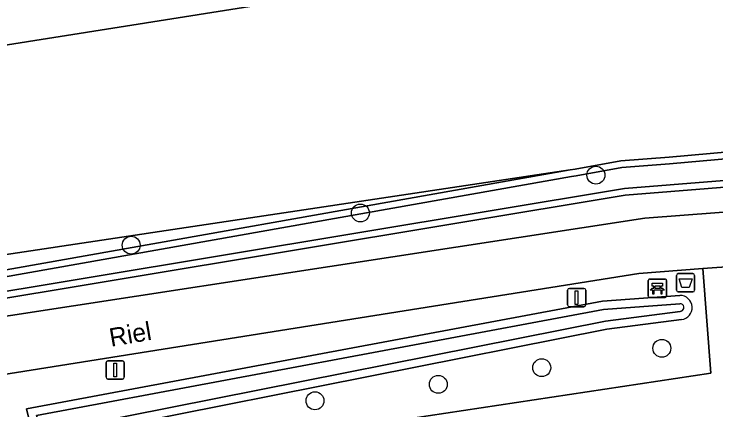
# Model space of a CAD drawing. Extents: x 163426 to 164192, y 380329 to 381641.
# Drawn here: x 163764.55 to 163802.83, y 381000.75 to 381022.35 of the extents above; entities that cross this region are included whole.
import ezdxf

# ---------------------------------------------------------------- set-up
doc = ezdxf.new("R2010")
doc.units = 0
for name, color, linetype in [('IMGEO_Afvalbak', 7, 'Continuous'), ('IMGEO_Bank', 7, 'Continuous'), ('IMGEO_Boom', 7, 'Continuous'), ('IMGEO_Fietspad_gesloten', 7, 'Continuous'), ('IMGEO_Groenvoorziening', 7, 'Continuous'), ('IMGEO_Hek', 7, 'Continuous'), ('IMGEO_Lichtmast', 7, 'Continuous'), ('IMGEO_Oever', 7, 'Continuous'), ('IMGEO_Openbare_ruimte_label', 7, 'Continuous'), ('IMGEO_Voetpad_halfverhard', 7, 'Continuous'), ('IMGEO_Voetpad_open', 7, 'Continuous'), ('IMGEO_Waterloop', 7, 'Continuous')]:
    doc.layers.add(name, color=color, linetype=linetype)

msp = doc.modelspace()

# ---------------------------------------------------------------- linework, layer by layer
at = {"layer": 'IMGEO_Afvalbak'}
for p, q in [((163800.678, 381007.292), (163800.678, 381008.092)), ((163800.678, 381008.092), (163800.678, 381007.292)), ((163800.778, 381008.192), (163801.568, 381008.192)), ((163801.568, 381008.192), (163800.778, 381008.192)), ((163801.668, 381008.092), (163801.668, 381007.292)), ((163801.668, 381007.292), (163801.668, 381008.092)), ((163801.568, 381007.192), (163800.778, 381007.192)), ((163800.778, 381007.192), (163801.568, 381007.192))]:
    msp.add_line(p, q, dxfattribs=at)
msp.add_lwpolyline([(163800.821, 381007.906), (163801.525, 381007.906), (163801.376, 381007.436), (163800.97, 381007.436), (163800.821, 381007.906)], dxfattribs=at)
for centre, start, end in [((163800.778, 381008.092), 90, 180), ((163800.778, 381008.092), 90, 180), ((163801.568, 381008.092), 0, 90), ((163801.568, 381008.092), 360, 90), ((163800.778, 381007.292), 180, 270), ((163800.778, 381007.292), 180, 270), ((163801.568, 381007.292), 270, 0), ((163801.568, 381007.292), 270, 0)]:
    msp.add_arc(centre, 0.1, start, end, dxfattribs=at)
at = {"layer": 'IMGEO_Bank'}
for p, q in [((163799.216, 381007.89), (163800.057, 381007.89)), ((163800.057, 381007.89), (163799.216, 381007.89)), ((163799.141, 381006.965), (163799.141, 381007.806)), ((163799.141, 381007.806), (163799.141, 381006.965)), ((163799.45, 381007.396), (163799.45, 381007.502)), ((163799.494, 381007.502), (163799.494, 381007.396)), ((163799.782, 381007.508), (163799.5, 381007.508)), ((163799.788, 381007.396), (163799.788, 381007.502)), ((163799.832, 381007.502), (163799.832, 381007.396)), ((163800.141, 381007.815), (163800.141, 381006.974)), ((163800.141, 381006.974), (163800.141, 381007.815)), ((163799.838, 381007.288), (163799.445, 381007.288)), ((163799.5, 381007.39), (163799.782, 381007.39)), ((163800.066, 381006.89), (163799.225, 381006.89)), ((163799.225, 381006.89), (163800.066, 381006.89))]:
    msp.add_line(p, q, dxfattribs=at)
for points in [[(163799.444, 381007.508), (163799.358, 381007.508), (163799.358, 381007.669), (163799.921, 381007.669), (163799.921, 381007.508), (163799.838, 381007.508)], [(163799.388, 381007.288), (163799.246, 381007.288), (163799.358, 381007.39), (163799.444, 381007.39)], [(163799.438, 381007.281), (163799.438, 381007.074), (163799.395, 381007.074), (163799.395, 381007.281)], [(163799.838, 381007.39), (163799.921, 381007.39), (163800.033, 381007.288), (163799.894, 381007.288)], [(163799.888, 381007.281), (163799.888, 381007.074), (163799.844, 381007.074), (163799.844, 381007.281)]]:
    msp.add_lwpolyline(points, dxfattribs=at)
for centre, radius, start, end in [((163799.219, 381007.812), 0.0779, 92.4484, 184.2845), ((163799.219, 381007.812), 0.0779, 92.4484, 184.2845), ((163800.063, 381007.812), 0.0779, 2.4484, 94.2845), ((163800.063, 381007.812), 0.0779, 2.4484, 94.2845), ((163799.443, 381007.501), 0.00671, 2.8957, 87.1043), ((163799.5, 381007.501), 0.00671, 92.8957, 177.1043), ((163799.782, 381007.501), 0.00671, 2.8957, 87.1043), ((163799.839, 381007.501), 0.00671, 92.8957, 177.1043), ((163799.388, 381007.281), 0.00671, 2.8957, 87.1043), ((163799.445, 381007.281), 0.00671, 92.8957, 177.1043), ((163799.443, 381007.397), 0.00671, 272.8957, 357.1043), ((163799.5, 381007.397), 0.00671, 182.8957, 267.1043), ((163799.782, 381007.397), 0.00671, 272.8957, 357.1043), ((163799.839, 381007.397), 0.00671, 182.8957, 267.1043), ((163799.837, 381007.281), 0.00671, 2.8957, 87.1043), ((163799.894, 381007.281), 0.00671, 92.8957, 177.1043), ((163799.219, 381006.968), 0.0779, 182.4484, 274.2845), ((163799.219, 381006.968), 0.0779, 182.4484, 274.2845), ((163800.063, 381006.968), 0.0779, 272.4484, 4.2845), ((163800.063, 381006.968), 0.0779, 272.4484, 4.2845)]:
    msp.add_arc(centre, radius, start, end, dxfattribs=at)
at = {"layer": 'IMGEO_Boom'}
for centre in [(163796.284, 381013.563), (163783.438, 381011.498), (163770.939, 381009.741), (163799.88, 381004.114), (163793.329, 381003.058), (163787.689, 381002.149), (163780.963, 381001.252)]:
    msp.add_circle(centre, 0.489, dxfattribs=at)
at = {"layer": 'IMGEO_Fietspad_gesloten'}
msp.add_lwpolyline([(163798.617, 381008.195), (163802.117, 381008.461), (163803.909, 381008.598), (163837.358, 381011.143), (163841.843, 381011.436), (163841.646, 381014.473), (163798.95, 381011.221), (163750.595, 381003.795), (163739.058, 381002.067), (163726.494, 381000), (163720.063, 380998.942), (163713.882, 380997.77), (163709.32, 380997.059), (163710.283, 380993.655), (163740.992, 380998.833), (163763.066, 381002.537)], close=True, dxfattribs=at)
at = {"layer": 'IMGEO_Groenvoorziening'}
for points in [[(163822.563, 381029.927), (163763.854, 381020.612), (163760.495, 381018.888), (163737.506, 381014.49), (163738.82, 381005.439), (163794.886, 381013.846), (163795.15, 381013.89), (163797.645, 381014.335), (163800.272, 381014.541), (163803.735, 381014.854), (163820.166, 381016.094), (163832.877, 381017.087), (163835.244, 381016.916), (163841.691, 381017.267), (163841.374, 381020.725), (163839.519, 381040.942)], [(163832.964, 381015.283), (163797.885, 381012.478), (163761.245, 381006.381), (163739.631, 381003.064), (163739.378, 381004.564), (163761.025, 381007.844), (163794.886, 381013.846), (163738.82, 381005.439), (163739.058, 381002.067), (163750.595, 381003.795), (163798.95, 381011.221), (163841.646, 381014.473)], [(163784.239, 381000), (163802.549, 381002.756), (163802.117, 381008.461), (163798.617, 381008.195), (163763.066, 381002.537), (163740.992, 380998.833), (163710.283, 380993.655), (163707.734, 380992.722), (163707.816, 380992.446)], [(163765.232, 381000.805), (163796.637, 381006.679), (163800.866, 381006.999)], [(163800.951, 381005.682), (163796.872, 381005.159), (163770.884, 381000), (163765.67, 380998.965), (163765.424, 381000), (163765.232, 381000.805)]]:
    msp.add_lwpolyline(points, dxfattribs=at)
msp.add_arc((163800.87, 381006.338), 0.661, 277.002, 90.3836, dxfattribs=at)
at = {"layer": 'IMGEO_Hek'}
msp.add_lwpolyline([(163794.886, 381013.846), (163738.82, 381005.439)], dxfattribs=at)
at = {"layer": 'IMGEO_Lichtmast'}
for p, q in [((163794.736, 381006.482), (163794.736, 381007.282)), ((163794.736, 381007.282), (163794.736, 381006.482)), ((163794.836, 381007.382), (163795.626, 381007.382)), ((163795.626, 381007.382), (163794.836, 381007.382)), ((163795.726, 381007.282), (163795.726, 381006.482)), ((163795.726, 381006.482), (163795.726, 381007.282)), ((163795.626, 381006.382), (163794.836, 381006.382)), ((163794.836, 381006.382), (163795.626, 381006.382)), ((163769.57, 381002.533), (163769.57, 381003.333)), ((163769.57, 381003.333), (163769.57, 381002.533)), ((163769.67, 381003.433), (163770.46, 381003.433)), ((163770.46, 381003.433), (163769.67, 381003.433)), ((163770.56, 381003.333), (163770.56, 381002.533)), ((163770.56, 381002.533), (163770.56, 381003.333)), ((163770.46, 381002.433), (163769.67, 381002.433)), ((163769.67, 381002.433), (163770.46, 381002.433))]:
    msp.add_line(p, q, dxfattribs=at)
for points in [[(163795.156, 381007.257), (163795.306, 381007.257), (163795.306, 381006.507), (163795.156, 381006.507), (163795.156, 381007.257)], [(163769.99, 381003.308), (163770.14, 381003.308), (163770.14, 381002.558), (163769.99, 381002.558), (163769.99, 381003.308)]]:
    msp.add_lwpolyline(points, dxfattribs=at)
for centre, start, end in [((163794.836, 381007.282), 90, 180), ((163794.836, 381007.282), 90, 180), ((163795.626, 381007.282), 0, 90), ((163795.626, 381007.282), 360, 90), ((163794.836, 381006.482), 180, 270), ((163794.836, 381006.482), 180, 270), ((163795.626, 381006.482), 270, 0), ((163795.626, 381006.482), 270, 0), ((163769.67, 381003.333), 90, 180), ((163769.67, 381003.333), 90, 180), ((163770.46, 381003.333), 0, 90), ((163770.46, 381003.333), 360, 90), ((163769.67, 381002.533), 180, 270), ((163769.67, 381002.533), 180, 270), ((163770.46, 381002.533), 270, 0), ((163770.46, 381002.533), 270, 0)]:
    msp.add_arc(centre, 0.1, start, end, dxfattribs=at)
at = {"layer": 'IMGEO_Oever'}
for points in [[(163832.964, 381015.283), (163841.715, 381015.283), (163841.825, 381016.439), (163835.244, 381016.916), (163832.877, 381017.087), (163820.166, 381016.094), (163803.735, 381014.854), (163800.272, 381014.541), (163797.645, 381014.335), (163795.15, 381013.89), (163794.886, 381013.846), (163761.025, 381007.844), (163739.378, 381004.564), (163739.631, 381003.064), (163761.245, 381006.381), (163797.885, 381012.478)], [(163841.425, 381016.101), (163841.382, 381015.649), (163832.949, 381015.649), (163797.84, 381012.842), (163761.187, 381006.742), (163739.932, 381003.48), (163739.801, 381004.258), (163761.084, 381007.483), (163794.948, 381013.485), (163795.212, 381013.529), (163797.692, 381013.972), (163800.303, 381014.176), (163803.765, 381014.489), (163820.194, 381015.729), (163832.878, 381016.72), (163835.218, 381016.551)]]:
    msp.add_lwpolyline(points, close=True, dxfattribs=at)
for points in [[(163800.866, 381006.999), (163796.637, 381006.679), (163765.232, 381000.805), (163765.424, 381000), (163765.67, 380998.965), (163770.884, 381000), (163796.872, 381005.159)], [(163796.8, 381005.601), (163770.797, 381000.439), (163766.006, 380999.488), (163765.859, 381000.104), (163765.776, 381000.452), (163796.695, 381006.235), (163800.866, 381006.55)], [(163800.931, 381006.135), (163800.877, 381006.123), (163796.8, 381005.601)], [(163796.872, 381005.159), (163800.951, 381005.682)]]:
    msp.add_lwpolyline(points, dxfattribs=at)
for centre, radius, start, end in [((163800.87, 381006.338), 0.661, 277.002, 90.3836), ((163800.871, 381006.338), 0.212, 286.5799, 91.2235)]:
    msp.add_arc(centre, radius, start, end, dxfattribs=at)
at = {"layer": 'IMGEO_Voetpad_halfverhard'}
msp.add_lwpolyline([(163810.663, 381080.58), (163820.163, 381032.72), (163762.988, 381022.55), (163736.984, 381018.089), (163737.506, 381014.49), (163760.495, 381018.888), (163763.854, 381020.612), (163822.563, 381029.927), (163812.477, 381080.889)], close=True, dxfattribs=at)
at = {"layer": 'IMGEO_Voetpad_open'}
msp.add_lwpolyline([(163804.54, 381000), (163804.103, 381005.949), (163803.909, 381008.598), (163802.117, 381008.461), (163802.549, 381002.756), (163784.239, 381000), (163713.192, 380989.306)], dxfattribs=at)
at = {"layer": 'IMGEO_Waterloop'}
msp.add_lwpolyline([(163841.425, 381016.101), (163835.218, 381016.551), (163832.878, 381016.72), (163820.194, 381015.729), (163803.765, 381014.489), (163800.303, 381014.176), (163797.692, 381013.972), (163795.212, 381013.529), (163794.948, 381013.485), (163761.084, 381007.483), (163739.801, 381004.258), (163739.932, 381003.48), (163761.187, 381006.742), (163797.84, 381012.842), (163832.949, 381015.649), (163841.382, 381015.649)], close=True, dxfattribs=at)
for points in [[(163800.866, 381006.55), (163796.695, 381006.235), (163765.776, 381000.452), (163765.859, 381000.104), (163766.006, 380999.488), (163770.797, 381000.439), (163796.8, 381005.601)], [(163796.8, 381005.601), (163800.877, 381006.123), (163800.931, 381006.135)]]:
    msp.add_lwpolyline(points, dxfattribs=at)
msp.add_arc((163800.871, 381006.338), 0.212, 286.5799, 91.2235, dxfattribs=at)

# ---------------------------------------------------------------- texts
at = {"layer": 'IMGEO_Openbare_ruimte_label'}
msp.add_text('Riel', height=1, rotation=9.8486, dxfattribs=at).set_placement((163769.837, 381004.196))

doc.saveas('drawing.dxf')
